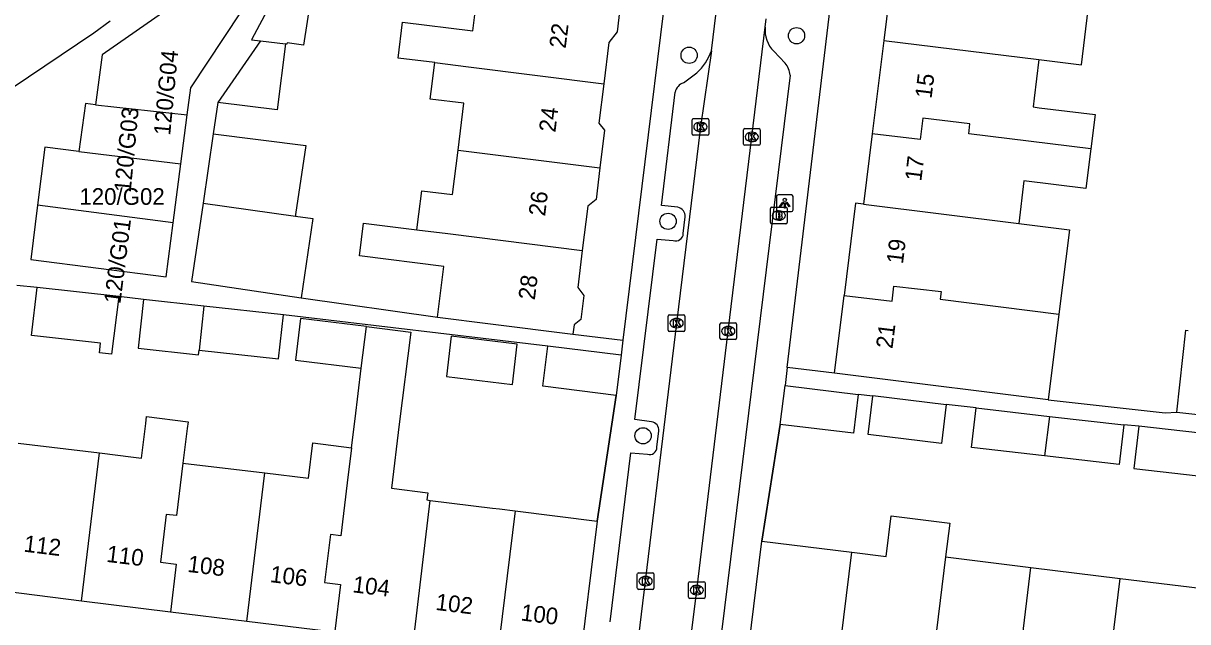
# Model space of a CAD drawing. Extents: x 158087 to 159494, y 382905 to 383981.
# Drawn here: x 158208.9 to 158278.9, y 383295.1 to 383331.1 of the extents above; entities that cross this region are included whole.
import ezdxf

# ---------------------------------------------------------------- set-up
doc = ezdxf.new("R2010")
doc.units = 0
for name, color, linetype in [('IMGEO_Boom', 7, 'Continuous'), ('IMGEO_Brandkraan', 7, 'Continuous'), ('IMGEO_Kolk', 7, 'Continuous'), ('IMGEO_Lichtpunt', 7, 'Continuous'), ('IMGEO_Muur', 7, 'Continuous'), ('IMGEO_Pand', 7, 'Continuous'), ('IMGEO_Pand_nummerreeks', 7, 'Continuous'), ('IMGEO_Rijbaan_lokaal_open', 7, 'Continuous'), ('IMGEO_Voetpad_open', 7, 'Continuous')]:
    doc.layers.add(name, color=color, linetype=linetype)

msp = doc.modelspace()

# ---------------------------------------------------------------- linework, layer by layer
at = {"layer": 'IMGEO_Boom'}
for centre in [(158255.407, 383330.346), (158248.951, 383329.172), (158247.683, 383319.193), (158246.181, 383306.304)]:
    msp.add_circle(centre, 0.489, dxfattribs=at)
at = {"layer": 'IMGEO_Brandkraan'}
for p, q in [((158253.843, 383319.117), (158253.843, 383319.969)), ((158253.918, 383320.043), (158254.77, 383320.043)), ((158254.844, 383319.969), (158254.844, 383319.117)), ((158254.354, 383319.263), (158254.329, 383319.263)), ((158254.331, 383319.823), (158254.356, 383319.823)), ((158254.77, 383319.043), (158253.918, 383319.043))]:
    msp.add_line(p, q, dxfattribs=at)
for points in [[(158253.843, 383319.117), (158253.843, 383319.969)], [(158253.918, 383320.043), (158254.77, 383320.043)], [(158254.844, 383319.969), (158254.844, 383319.117)], [(158254.191, 383319.743), (158254.191, 383319.343), (158254.404, 383319.343)], [(158254.422, 383319.743), (158254.191, 383319.743)], [(158254.37, 383319.662), (158254.316, 383319.662), (158254.316, 383319.586)], [(158254.316, 383319.586), (158254.369, 383319.586)], [(158254.378, 383319.51), (158254.316, 383319.51), (158254.316, 383319.429)], [(158254.316, 383319.429), (158254.378, 383319.429)], [(158254.77, 383319.043), (158253.918, 383319.043)]]:
    msp.add_lwpolyline(points, dxfattribs=at)
for centre, radius, start, end in [((158253.92, 383319.967), 0.0765, 91.55205, 178.44795), ((158253.92, 383319.967), 0.0765, 91.55205, 178.44795), ((158254.768, 383319.967), 0.0765, 1.55205, 88.44795), ((158254.768, 383319.967), 0.0765, 1.55205, 88.44795), ((158254.371, 383319.624), 0.0379, 267.82845, 90.93552), ((158254.379, 383319.469), 0.0404, 269.87594, 90.50774), ((158254.41, 383319.594), 0.251, 268.66757, 293.53466), ((158254.426, 383319.598), 0.145, 59.4692, 91.53667), ((158254.451, 383319.645), 0.0922, 285.51372, 58.15012), ((158254.456, 383319.453), 0.105, 301.31148, 78.98903), ((158253.92, 383319.119), 0.0765, 181.55205, 268.44795), ((158253.92, 383319.119), 0.0765, 181.55205, 268.44795), ((158254.768, 383319.119), 0.0765, 271.55205, 358.44795), ((158254.768, 383319.119), 0.0765, 271.55205, 358.44795)]:
    msp.add_arc(centre, radius, start, end, dxfattribs=at)
for centre, major_axis, ratio, start_param, end_param in [((158254.33, 383319.543), (-0.387, 0.002), 0.722429, 4.712389, 7.853982), ((158254.355, 383319.543), (-0.39, 0.002), 0.717154, 1.570796, 4.712389)]:
    msp.add_ellipse(centre, major_axis=major_axis, ratio=ratio, start_param=start_param, end_param=end_param, dxfattribs=at)
at = {"layer": 'IMGEO_Kolk'}
for p, q in [((158249.126, 383324.437), (158249.126, 383325.289)), ((158249.201, 383325.363), (158250.053, 383325.363)), ((158249.614, 383325.143), (158249.639, 383325.143)), ((158250.127, 383325.289), (158250.127, 383324.437)), ((158250.053, 383324.363), (158249.201, 383324.363)), ((158249.637, 383324.583), (158249.612, 383324.583)), ((158252.218, 383323.836), (158252.218, 383324.688)), ((158252.293, 383324.762), (158253.145, 383324.762)), ((158252.706, 383324.542), (158252.731, 383324.542)), ((158253.219, 383324.688), (158253.219, 383323.836)), ((158253.145, 383323.762), (158252.293, 383323.762)), ((158252.729, 383323.982), (158252.704, 383323.982)), ((158247.696, 383312.649), (158247.696, 383313.501)), ((158247.771, 383313.575), (158248.623, 383313.575)), ((158248.184, 383313.355), (158248.209, 383313.355)), ((158248.697, 383313.501), (158248.697, 383312.649)), ((158250.804, 383312.17), (158250.804, 383313.022)), ((158250.879, 383313.096), (158251.731, 383313.096)), ((158251.805, 383313.022), (158251.805, 383312.17)), ((158248.623, 383312.575), (158247.771, 383312.575)), ((158248.207, 383312.795), (158248.182, 383312.795)), ((158251.315, 383312.316), (158251.29, 383312.316)), ((158251.292, 383312.876), (158251.317, 383312.876)), ((158251.731, 383312.096), (158250.879, 383312.096)), ((158245.835, 383297.149), (158245.835, 383298.001)), ((158245.91, 383298.075), (158246.762, 383298.075)), ((158246.323, 383297.855), (158246.348, 383297.855)), ((158246.836, 383298.001), (158246.836, 383297.149)), ((158246.762, 383297.075), (158245.91, 383297.075)), ((158246.346, 383297.295), (158246.321, 383297.295)), ((158248.911, 383296.611), (158248.911, 383297.463)), ((158248.986, 383297.537), (158249.838, 383297.537)), ((158249.399, 383297.317), (158249.424, 383297.317)), ((158249.912, 383297.463), (158249.912, 383296.611)), ((158249.838, 383296.537), (158248.986, 383296.537)), ((158249.422, 383296.757), (158249.397, 383296.757))]:
    msp.add_line(p, q, dxfattribs=at)
for points in [[(158249.126, 383324.437), (158249.126, 383325.289)], [(158249.201, 383325.363), (158250.053, 383325.363)], [(158249.447, 383325.063), (158249.57, 383325.063), (158249.57, 383324.912), (158249.7, 383325.063), (158249.864, 383325.063), (158249.718, 383324.912), (158249.871, 383324.663), (158249.719, 383324.663), (158249.634, 383324.827), (158249.57, 383324.76), (158249.57, 383324.663), (158249.447, 383324.663), (158249.447, 383325.063)], [(158250.127, 383325.289), (158250.127, 383324.437)], [(158250.053, 383324.363), (158249.201, 383324.363)], [(158252.218, 383323.836), (158252.218, 383324.688)], [(158252.293, 383324.762), (158253.145, 383324.762)], [(158252.539, 383324.462), (158252.662, 383324.462), (158252.662, 383324.311), (158252.792, 383324.462), (158252.956, 383324.462), (158252.81, 383324.311), (158252.963, 383324.062), (158252.811, 383324.062), (158252.726, 383324.226), (158252.662, 383324.159), (158252.662, 383324.062), (158252.539, 383324.062), (158252.539, 383324.462)], [(158253.219, 383324.688), (158253.219, 383323.836)], [(158253.145, 383323.762), (158252.293, 383323.762)], [(158247.696, 383312.649), (158247.696, 383313.501)], [(158247.771, 383313.575), (158248.623, 383313.575)], [(158248.017, 383313.275), (158248.14, 383313.275), (158248.14, 383313.124), (158248.27, 383313.275), (158248.434, 383313.275), (158248.288, 383313.124), (158248.441, 383312.875), (158248.289, 383312.875), (158248.204, 383313.039), (158248.14, 383312.972), (158248.14, 383312.875), (158248.017, 383312.875), (158248.017, 383313.275)], [(158248.697, 383313.501), (158248.697, 383312.649)], [(158250.804, 383312.17), (158250.804, 383313.022)], [(158250.879, 383313.096), (158251.731, 383313.096)], [(158251.805, 383313.022), (158251.805, 383312.17)], [(158248.623, 383312.575), (158247.771, 383312.575)], [(158251.125, 383312.796), (158251.248, 383312.796), (158251.248, 383312.645), (158251.378, 383312.796), (158251.542, 383312.796), (158251.396, 383312.645), (158251.549, 383312.396), (158251.397, 383312.396), (158251.312, 383312.56), (158251.248, 383312.493), (158251.248, 383312.396), (158251.125, 383312.396), (158251.125, 383312.796)], [(158251.731, 383312.096), (158250.879, 383312.096)], [(158245.835, 383297.149), (158245.835, 383298.001)], [(158245.91, 383298.075), (158246.762, 383298.075)], [(158246.156, 383297.775), (158246.279, 383297.775), (158246.279, 383297.624), (158246.409, 383297.775), (158246.573, 383297.775), (158246.427, 383297.624), (158246.58, 383297.375), (158246.428, 383297.375), (158246.343, 383297.539), (158246.279, 383297.472), (158246.279, 383297.375), (158246.156, 383297.375), (158246.156, 383297.775)], [(158246.836, 383298.001), (158246.836, 383297.149)], [(158246.762, 383297.075), (158245.91, 383297.075)], [(158248.911, 383296.611), (158248.911, 383297.463)], [(158248.986, 383297.537), (158249.838, 383297.537)], [(158249.232, 383297.237), (158249.355, 383297.237), (158249.355, 383297.086), (158249.485, 383297.237), (158249.649, 383297.237), (158249.503, 383297.086), (158249.656, 383296.837), (158249.504, 383296.837), (158249.419, 383297.001), (158249.355, 383296.934), (158249.355, 383296.837), (158249.232, 383296.837), (158249.232, 383297.237)], [(158249.912, 383297.463), (158249.912, 383296.611)], [(158249.838, 383296.537), (158248.986, 383296.537)]]:
    msp.add_lwpolyline(points, dxfattribs=at)
for centre, start, end in [((158249.203, 383325.287), 91.55205, 178.44795), ((158249.203, 383325.287), 91.55205, 178.44795), ((158250.051, 383325.287), 1.55205, 88.44795), ((158250.051, 383325.287), 1.55205, 88.44795), ((158249.203, 383324.439), 181.55205, 268.44795), ((158249.203, 383324.439), 181.55205, 268.44795), ((158250.051, 383324.439), 271.55205, 358.44795), ((158250.051, 383324.439), 271.55205, 358.44795), ((158252.295, 383324.686), 91.55205, 178.44795), ((158252.295, 383324.686), 91.55205, 178.44795), ((158253.143, 383324.686), 1.55205, 88.44795), ((158253.143, 383324.686), 1.55205, 88.44795), ((158252.295, 383323.838), 181.55205, 268.44795), ((158252.295, 383323.838), 181.55205, 268.44795), ((158253.143, 383323.838), 271.55205, 358.44795), ((158253.143, 383323.838), 271.55205, 358.44795), ((158247.773, 383313.499), 91.55205, 178.44795), ((158247.773, 383313.499), 91.55205, 178.44795), ((158248.621, 383313.499), 1.55205, 88.44795), ((158248.621, 383313.499), 1.55205, 88.44795), ((158250.881, 383313.02), 91.55205, 178.44795), ((158250.881, 383313.02), 91.55205, 178.44795), ((158251.729, 383313.02), 1.55205, 88.44795), ((158251.729, 383313.02), 1.55205, 88.44795), ((158247.773, 383312.651), 181.55205, 268.44795), ((158247.773, 383312.651), 181.55205, 268.44795), ((158248.621, 383312.651), 271.55205, 358.44795), ((158248.621, 383312.651), 271.55205, 358.44795), ((158250.881, 383312.172), 181.55205, 268.44795), ((158250.881, 383312.172), 181.55205, 268.44795), ((158251.729, 383312.172), 271.55205, 358.44795), ((158251.729, 383312.172), 271.55205, 358.44795), ((158245.912, 383297.999), 91.55205, 178.44795), ((158245.912, 383297.999), 91.55205, 178.44795), ((158246.76, 383297.999), 1.55205, 88.44795), ((158246.76, 383297.999), 1.55205, 88.44795), ((158245.912, 383297.151), 181.55205, 268.44795), ((158245.912, 383297.151), 181.55205, 268.44795), ((158246.76, 383297.151), 271.55205, 358.44795), ((158246.76, 383297.151), 271.55205, 358.44795), ((158248.988, 383297.461), 91.55205, 178.44795), ((158248.988, 383297.461), 91.55205, 178.44795), ((158249.836, 383297.461), 1.55205, 88.44795), ((158249.836, 383297.461), 1.55205, 88.44795), ((158248.988, 383296.613), 181.55205, 268.44795), ((158248.988, 383296.613), 181.55205, 268.44795), ((158249.836, 383296.613), 271.55205, 358.44795), ((158249.836, 383296.613), 271.55205, 358.44795)]:
    msp.add_arc(centre, 0.0765, start, end, dxfattribs=at)
for centre, major_axis, ratio, start_param, end_param in [((158249.613, 383324.863), (-0.387, 0.002), 0.722429, 4.712389, 7.853982), ((158249.638, 383324.863), (-0.39, 0.002), 0.717154, 1.570796, 4.712389), ((158252.705, 383324.262), (-0.387, 0.002), 0.722429, 4.712389, 7.853982), ((158252.73, 383324.262), (-0.39, 0.002), 0.717154, 1.570796, 4.712389), ((158248.183, 383313.075), (-0.387, 0.002), 0.722429, 4.712389, 7.853982), ((158248.208, 383313.075), (-0.39, 0.002), 0.717154, 1.570796, 4.712389), ((158251.291, 383312.596), (-0.387, 0.002), 0.722429, 4.712389, 7.853982), ((158251.316, 383312.596), (-0.39, 0.002), 0.717154, 1.570796, 4.712389), ((158246.322, 383297.575), (-0.387, 0.002), 0.722429, 4.712389, 7.853982), ((158246.347, 383297.575), (-0.39, 0.002), 0.717154, 1.570796, 4.712389), ((158249.398, 383297.037), (-0.387, 0.002), 0.722429, 4.712389, 7.853982), ((158249.423, 383297.037), (-0.39, 0.002), 0.717154, 1.570796, 4.712389)]:
    msp.add_ellipse(centre, major_axis=major_axis, ratio=ratio, start_param=start_param, end_param=end_param, dxfattribs=at)
at = {"layer": 'IMGEO_Lichtpunt'}
for p, q in [((158254.202, 383320.686), (158254.202, 383319.879)), ((158254.202, 383320.686), (158254.202, 383319.879)), ((158255.104, 383320.781), (158254.296, 383320.781)), ((158255.104, 383320.781), (158254.296, 383320.781)), ((158255.198, 383319.879), (158255.198, 383320.686)), ((158255.198, 383319.879), (158255.198, 383320.686)), ((158254.296, 383319.785), (158255.104, 383319.785)), ((158254.296, 383319.785), (158255.104, 383319.785))]:
    msp.add_line(p, q, dxfattribs=at)
for points in [[(158254.576, 383320.35), (158254.615, 383320.322), (158254.427, 383320.06), (158254.389, 383320.087), (158254.576, 383320.35)], [(158254.678, 383320.302), (158254.725, 383320.302), (158254.725, 383319.98), (158254.678, 383319.98), (158254.678, 383320.302)], [(158254.788, 383320.322), (158254.826, 383320.349), (158255.013, 383320.087), (158254.974, 383320.059), (158254.788, 383320.322)]]:
    msp.add_lwpolyline(points, dxfattribs=at)
msp.add_circle((158254.701, 383320.484), 0.0994, dxfattribs=at)
for centre, start, end in [((158254.296, 383320.686), 90, 180), ((158254.296, 383320.686), 90, 180), ((158255.104, 383320.686), 0, 90), ((158255.104, 383320.686), 0, 90), ((158254.296, 383319.879), 180, 270), ((158254.296, 383319.879), 180, 270), ((158255.104, 383319.879), 270, 0), ((158255.104, 383319.879), 270, 360)]:
    msp.add_arc(centre, 0.0946, start, end, dxfattribs=at)
at = {"layer": 'IMGEO_Muur'}
for points in [[(158243.427, 383301.176), (158244.558, 383308.736)], [(158253.313, 383299.979), (158254.433, 383306.994)]]:
    msp.add_lwpolyline(points, dxfattribs=at)
at = {"layer": 'IMGEO_Pand'}
for points in [[(158218.772, 383325.599), (158218.982, 383327.205), (158223.006, 383333.289), (158221.37, 383334.581), (158213.649, 383329.189), (158213.263, 383326.202)], [(158225.321, 383334.187), (158224.849, 383334.237), (158222.636, 383330.105), (158223.174, 383330.038)], [(158225.321, 383334.187), (158226.417, 383334.071), (158225.755, 383329.77), (158224.779, 383329.913), (158224.768, 383329.839), (158224.678, 383329.85)], [(158261.158, 383334.144), (158260.653, 383330.066)], [(158233.651, 383328.731), (158231.447, 383329.005), (158231.714, 383331.169), (158235.946, 383330.645), (158236.304, 383333.54)], [(158269.986, 383328.912), (158272.533, 383328.597), (158273.151, 383333.596), (158273.002, 383333.614)], [(158244.848, 383332.474), (158244.614, 383330.581), (158244.127, 383329.936), (158243.821, 383327.463)], [(158223.174, 383330.038), (158220.615, 383326.331)], [(158224.678, 383329.85), (158224.188, 383325.889), (158220.615, 383326.331)], [(158223.174, 383330.038), (158224.678, 383329.85)], [(158260.653, 383330.066), (158259.959, 383324.451)], [(158260.653, 383330.066), (158269.986, 383328.912)], [(158235.059, 383323.474), (158235.407, 383326.289), (158233.386, 383326.539), (158233.435, 383327.001), (158233.651, 383328.731)], [(158233.651, 383328.731), (158235.678, 383328.478), (158243.821, 383327.463)], [(158269.986, 383328.912), (158269.7, 383326.596), (158269.634, 383326.063), (158270, 383326.018), (158273.356, 383325.602), (158273.103, 383323.551)], [(158243.821, 383327.463), (158243.529, 383325.098), (158243.866, 383324.666), (158243.587, 383322.411)], [(158213.263, 383326.202), (158212.651, 383326.269), (158212.244, 383323.397)], [(158213.263, 383326.202), (158218.772, 383325.599)], [(158218.388, 383322.65), (158218.772, 383325.599)], [(158273.103, 383323.551), (158265.762, 383324.46), (158265.834, 383325.051), (158262.995, 383325.397), (158262.837, 383324.101), (158259.959, 383324.451)], [(158220.339, 383324.451), (158219.727, 383320.286)], [(158220.339, 383324.451), (158225.898, 383323.758), (158225.286, 383319.593), (158225.274, 383319.512)], [(158259.959, 383324.451), (158259.436, 383320.225)], [(158212.244, 383323.397), (158210.204, 383323.645), (158209.773, 383320.166)], [(158232.578, 383318.684), (158232.695, 383319.619), (158232.87, 383321.027), (158234.728, 383320.796), (158235.059, 383323.474)], [(158235.059, 383323.474), (158243.587, 383322.411)], [(158273.103, 383323.551), (158272.809, 383321.158), (158269.084, 383321.619), (158268.769, 383319.07)], [(158212.244, 383323.397), (158218.388, 383322.65)], [(158217.925, 383319.102), (158218.388, 383322.65)], [(158243.587, 383322.411), (158243.351, 383320.497), (158242.857, 383320.112), (158242.527, 383317.443)], [(158209.773, 383320.166), (158209.368, 383316.891), (158217.501, 383315.854), (158217.925, 383319.102)], [(158217.925, 383319.102), (158209.773, 383320.166)], [(158219.727, 383320.286), (158219.034, 383315.569), (158225.631, 383314.6)], [(158219.727, 383320.286), (158225.274, 383319.512)], [(158259.436, 383320.225), (158258.955, 383320.282), (158258.269, 383314.738)], [(158259.436, 383320.225), (158268.769, 383319.07)], [(158225.274, 383319.512), (158226.329, 383319.357), (158225.631, 383314.6)], [(158233.817, 383313.428), (158234.195, 383316.488), (158229.132, 383317.114), (158229.377, 383319.083), (158232.578, 383318.684)], [(158232.578, 383318.684), (158234.438, 383318.452), (158242.527, 383317.443)], [(158268.769, 383319.07), (158271.817, 383318.687), (158271.179, 383313.609)], [(158242.527, 383317.443), (158242.251, 383315.216), (158242.62, 383314.743), (158242.442, 383313.3), (158242.029, 383312.978), (158241.96, 383312.42)], [(158214.649, 383314.669), (158214.226, 383311.213), (158213.501, 383311.294), (158213.564, 383311.862), (158209.401, 383312.325), (158209.755, 383315.214)], [(158214.649, 383314.669), (158209.755, 383315.214)], [(158258.269, 383314.738), (158261.152, 383314.388), (158261.264, 383315.305), (158264.105, 383314.978), (158264.048, 383314.512), (158271.179, 383313.609)], [(158216.142, 383314.503), (158215.817, 383311.575), (158219.448, 383311.171), (158219.479, 383311.454)], [(158219.773, 383314.1), (158216.142, 383314.503)], [(158257.691, 383310.062), (158258.269, 383314.738)], [(158219.773, 383314.1), (158219.479, 383311.454)], [(158224.555, 383313.567), (158219.773, 383314.1)], [(158219.479, 383311.454), (158224.261, 383310.922), (158224.555, 383313.567)], [(158229.551, 383312.866), (158225.588, 383313.346), (158225.285, 383310.845), (158229.239, 383310.366)], [(158233.817, 383313.428), (158236.998, 383313.034), (158241.96, 383312.42)], [(158271.179, 383313.609), (158270.532, 383308.459)], [(158229.239, 383310.366), (158229.551, 383312.866)], [(158229.551, 383312.866), (158232.209, 383312.542), (158231.519, 383307.003), (158231.048, 383303.151), (158233.231, 383302.886), (158233.176, 383302.449), (158233.37, 383302.425)], [(158238.617, 383311.808), (158234.649, 383312.293), (158234.354, 383309.878), (158238.321, 383309.393), (158238.617, 383311.808)], [(158278.282, 383307.728), (158278.824, 383312.648), (158278.957, 383312.631)], [(158278.282, 383307.728), (158281.162, 383307.41), (158281.699, 383312.277)], [(158244.558, 383308.736), (158240.162, 383309.282), (158240.462, 383311.698)], [(158244.858, 383311.152), (158240.462, 383311.698)], [(158244.858, 383311.152), (158244.558, 383308.736)], [(158228.647, 383305.592), (158228.86, 383307.328), (158229.239, 383310.366)], [(158270.532, 383308.459), (158267.17, 383308.881), (158262.654, 383309.448), (158257.691, 383310.062)], [(158254.433, 383306.994), (158254.718, 383309.327)], [(158259.116, 383308.791), (158258.831, 383306.459), (158254.433, 383306.994)], [(158254.718, 383309.327), (158259.116, 383308.791)], [(158264.4, 383308.184), (158264.115, 383305.852), (158259.717, 383306.387), (158259.997, 383308.683)], [(158259.997, 383308.683), (158260.002, 383308.72), (158264.4, 383308.184)], [(158213.499, 383305.277), (158215.542, 383305.029), (158216.018, 383304.971), (158216.272, 383307.044), (158216.323, 383307.459), (158218.819, 383307.154), (158218.768, 383306.738), (158218.515, 383304.669)], [(158270.326, 383305.093), (158265.929, 383305.598), (158266.202, 383307.978)], [(158266.202, 383307.978), (158270.617, 383307.472)], [(158270.617, 383307.472), (158270.326, 383305.093)], [(158270.617, 383307.472), (158275.086, 383306.96)], [(158275.086, 383306.96), (158274.813, 383304.579), (158270.326, 383305.093)], [(158275.983, 383306.89), (158275.691, 383304.344), (158281.15, 383303.718)], [(158281.461, 383306.262), (158275.983, 383306.89)], [(158208.611, 383305.869), (158213.499, 383305.277)], [(158212.41, 383296.378), (158213.499, 383305.277)], [(158223.441, 383304.072), (158226.063, 383303.755), (158226.32, 383305.874), (158228.647, 383305.592)], [(158228.647, 383305.592), (158228.388, 383303.473), (158228, 383300.301), (158227.383, 383300.376), (158227.03, 383297.496), (158227.984, 383297.38), (158227.639, 383294.56)], [(158218.515, 383304.669), (158218.128, 383301.51), (158217.511, 383301.585), (158217.158, 383298.705), (158218.112, 383298.589), (158217.761, 383295.716)], [(158218.515, 383304.669), (158223.441, 383304.072)], [(158222.349, 383295.15), (158223.441, 383304.072)], [(158232.321, 383293.474), (158233.37, 383302.425)], [(158233.37, 383302.425), (158237.125, 383301.959), (158237.544, 383301.907), (158238.492, 383301.789)], [(158238.492, 383301.789), (158237.395, 383292.848)], [(158238.492, 383301.789), (158243.427, 383301.176)], [(158243.427, 383301.176), (158242.318, 383292.241)], [(158258.733, 383299.313), (158260.796, 383299.06), (158261.094, 383301.493), (158264.617, 383301.061), (158264.368, 383299.026)], [(158252.225, 383291.029), (158253.313, 383299.979)], [(158253.313, 383299.979), (158258.733, 383299.313)], [(158257.638, 383290.362), (158258.733, 383299.313)], [(158264.368, 383299.026), (158263.287, 383290.185)], [(158264.368, 383299.026), (158269.506, 383298.394)], [(158268.425, 383289.556), (158269.506, 383298.394)], [(158269.506, 383298.394), (158274.859, 383297.735)], [(158273.778, 383288.9), (158274.859, 383297.735)], [(158274.859, 383297.735), (158280.335, 383297.062)], [(158212.41, 383296.378), (158207.86, 383296.94)], [(158217.761, 383295.716), (158212.41, 383296.378)], [(158222.349, 383295.15), (158217.761, 383295.716)], [(158227.639, 383294.56), (158227.294, 383294.539), (158222.349, 383295.15)]]:
    msp.add_lwpolyline(points, dxfattribs=at)
at = {"layer": 'IMGEO_Rijbaan_lokaal_open'}
for points in [[(158250.288, 383329.438), (158250.566, 383331.749)], [(158253.526, 383330.865), (158253.584, 383331.362)], [(158248.331, 383288.334), (158249.411, 383297.038), (158251.304, 383312.596), (158252.719, 383324.263), (158253.526, 383330.865)], [(158250.288, 383329.438), (158249.628, 383324.862), (158248.198, 383313.075), (158245.651, 383292.117)]]:
    msp.add_lwpolyline(points, dxfattribs=at)
at = {"layer": 'IMGEO_Voetpad_open'}
for points in [[(158254.847, 383310.402), (158261.455, 383365.679)], [(158248.754, 383342.754), (158244.969, 383312.049)], [(158208.245, 383327.218), (158213.164, 383330.52), (158214.145, 383331.232)], [(158254.035, 383329.413), (158254.722, 383328.697)], [(158248.607, 383327.518), (158249.417, 383328.115)], [(158255.025, 383327.973), (158250.364, 383290.124)], [(158220.615, 383326.331), (158220.339, 383324.451)], [(158248.273, 383320.036), (158247.279, 383320.143), (158248.109, 383326.956)], [(158248.6, 383318.456), (158248.718, 383319.46)], [(158246.682, 383307.137), (158245.688, 383307.283), (158247.022, 383318.117), (158247.994, 383318.036)], [(158209.755, 383315.214), (158208.52, 383315.331)], [(158216.142, 383314.503), (158214.649, 383314.669)], [(158225.631, 383314.6), (158233.817, 383313.428)], [(158240.462, 383311.698), (158224.555, 383313.567)], [(158241.96, 383312.42), (158244.969, 383312.049)], [(158244.969, 383312.049), (158244.858, 383311.152)], [(158254.847, 383310.402), (158254.718, 383309.327)], [(158257.691, 383310.062), (158254.847, 383310.402)], [(158259.997, 383308.683), (158259.116, 383308.791)], [(158244.558, 383308.736), (158243.427, 383301.176)], [(158266.202, 383307.978), (158264.4, 383308.184)], [(158270.532, 383308.459), (158277.579, 383307.682), (158278.282, 383307.728)], [(158254.433, 383306.994), (158253.313, 383299.979)], [(158275.983, 383306.89), (158275.086, 383306.96)], [(158247.012, 383305.619), (158247.134, 383306.6)], [(158244.209, 383295.135), (158245.449, 383305.274), (158246.443, 383305.195)]]:
    msp.add_lwpolyline(points, dxfattribs=at)
for centre, radius, start, end in [((158255.353, 383330.69), 1.835, 174.53236, 224.10397), ((158247.206, 383330.519), 3.266, 312.60576, 340.67624), ((158253.652, 383327.824), 1.381, 6.20271, 39.21672), ((158248.837, 383326.812), 0.742, 108.0631, 168.84725), ((158248.163, 383319.491), 0.556, 356.75966, 78.6175), ((158248.135, 383318.48), 0.466, 252.39152, 357.05776), ((158246.648, 383306.65), 0.488, 354.15855, 86.01697), ((158246.572, 383305.616), 0.44, 252.96955, 0.41498)]:
    msp.add_arc(centre, radius, start, end, dxfattribs=at)

# ---------------------------------------------------------------- texts
at = {"layer": 'IMGEO_Pand_nummerreeks'}
for s, rotation, p in [('22', 82.99867, (158241.525, 383329.549)), ('120/G04', 84.53979, (158217.743, 383324.326)), ('15', 82.95283, (158263.522, 383326.535)), ('120/G03', 84.53979, (158215.37, 383320.897)), ('24', 82.99867, (158240.906, 383324.511)), ('17', 82.95283, (158262.908, 383321.574)), ('120/G02', 0, (158212.288, 383320.184)), ('26', 82.99867, (158240.286, 383319.469)), ('120/G01', 82.76016, (158214.749, 383314.204)), ('19', 82.94952, (158261.804, 383316.594)), ('28', 82.99867, (158239.668, 383314.431)), ('21', 82.94952, (158261.175, 383311.506)), ('112', 352.95835, (158208.901, 383299.35)), ('110', 352.95835, (158213.873, 383298.736)), ('108', 352.95835, (158218.75, 383298.133)), ('106', 352.95835, (158223.712, 383297.52)), ('104', 352.95835, (158228.678, 383296.906)), ('102', 352.96981, (158233.667, 383295.847)), ('100', 352.96934, (158238.793, 383295.215))]:
    msp.add_text(s, height=1, rotation=rotation, dxfattribs=at).set_placement(p)

doc.saveas('drawing.dxf')
